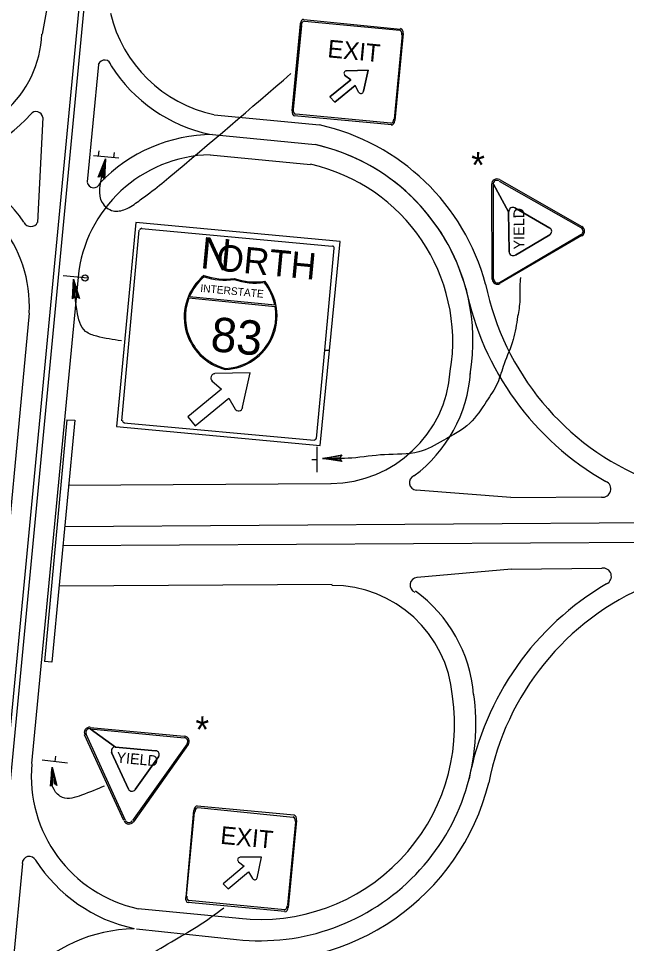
# Model space of a CAD drawing. Extents: x 640994 to 644422, y 298458 to 299646.
# Drawn here: x 641393.3 to 641528.1, y 298657.8 to 298862.8 of the extents above; entities that cross this region are included whole.
import ezdxf

# ---------------------------------------------------------------- set-up
doc = ezdxf.new("R2010")
doc.units = 0
doc.layers.add('2', color=7, linetype='Continuous')

msp = doc.modelspace()

# ---------------------------------------------------------------- linework, layer by layer
at = {"layer": '2'}
for p, q in [((641418.56, 298990.13), (641373.69, 298519.25)), ((641419.69, 298990.13), (641374.81, 298519.25)), ((641404.81, 298894.25), (641398.56, 298859.38)), ((641456.56, 298862.63), (641477.94, 298860.5)), ((641456.69, 298862.25), (641477.81, 298860.25)), ((641453.94, 298842.38), (641455.81, 298861.63)), ((641454.19, 298842.63), (641456.06, 298861.25)), ((641456.06, 298861.25), (641454.19, 298842.63)), ((641476.19, 298860.5), (641476.19, 298860.5)), ((641478.31, 298859.25), (641476.56, 298840.5)), ((641478.56, 298859.5), (641476.69, 298840.25)), ((641411.06, 298852.63), (641408.56, 298826.63)), ((641411.06, 298852.63), (641411.06, 298852.63)), ((641466.94, 298849.25), (641465.56, 298850.25)), ((641465.56, 298850.25), (641466.94, 298849.25)), ((641466.06, 298851.25), (641470.81, 298851.38)), ((641470.81, 298851.38), (641466.06, 298851.25)), ((641470.81, 298851.38), (641469.81, 298846.75)), ((641469.81, 298846.75), (641470.81, 298851.38)), ((641462.31, 298845.5), (641466.94, 298849.25)), ((641466.94, 298849.25), (641462.31, 298845.5)), ((641467.94, 298848), (641463.44, 298844.25)), ((641463.44, 298844.25), (641467.94, 298848)), ((641468.69, 298846.5), (641467.94, 298848)), ((641467.94, 298848), (641468.69, 298846.5)), ((641469.81, 298846.75), (641469.81, 298846.75)), ((641463.44, 298844.25), (641462.31, 298845.5)), ((641462.31, 298845.5), (641463.44, 298844.25)), ((641475.81, 298839.63), (641454.81, 298841.63)), ((641398.69, 298840.88), (641397.56, 298817.63)), ((641436.69, 298841.5), (641460.06, 298839.25)), ((641476.06, 298839.25), (641454.44, 298841.25)), ((641436.31, 298837.11), (641459.06, 298834.88)), ((641411.06, 298832.38), (641411.19, 298833.5)), ((641415.56, 298831.88), (641409.94, 298832.38)), ((641414.44, 298832), (641414.56, 298833.13)), ((641435.81, 298832.63), (641458.06, 298830.5)), ((641408.56, 298826.63), (641408.56, 298826.63)), ((641498.31, 298805), (641498.19, 298826.13)), ((641498.56, 298805), (641498.56, 298826.13)), ((641501.94, 298820), (641498.56, 298826.13)), ((641501.94, 298820), (641498.56, 298826.13)), ((641498.56, 298805), (641498.56, 298826.13)), ((641498.56, 298826.13), (641501.94, 298820)), ((641499.81, 298826.75), (641517.94, 298816.5)), ((641499.81, 298826.75), (641517.94, 298816.5)), ((641499.94, 298827.13), (641518.19, 298816.75)), ((641502.06, 298811.13), (641501.94, 298820)), ((641501.94, 298820), (641502.06, 298811.13)), ((641503.31, 298820.88), (641511.06, 298816.38)), ((641511.06, 298816.38), (641503.31, 298820.88)), ((641419.31, 298817.63), (641415.06, 298772.38)), ((641464.57, 298813.36), (641419.31, 298817.63)), ((641416.19, 298773.63), (641420.06, 298815.88)), ((641420.56, 298816.25), (641462.81, 298812.38)), ((641462.23, 298789.22), (641464.57, 298813.36)), ((641517.94, 298814.88), (641499.94, 298804.25)), ((641517.94, 298814.88), (641499.94, 298804.25)), ((641518.19, 298814.75), (641500.06, 298804.13)), ((641511.06, 298814.88), (641503.44, 298810.38)), ((641503.44, 298810.38), (641511.06, 298814.88)), ((641463.19, 298811.88), (641461.11, 298789.33)), ((641406.56, 298805.5), (641396.19, 298697.63)), ((641408.69, 298805.25), (641403.19, 298805.75)), ((641406.56, 298805.5), (641406.56, 298805.5)), ((641431.06, 298800.88), (641450.19, 298799)), ((641450.19, 298799.25), (641431.19, 298801.13)), ((641395.69, 298797.5), (641385.44, 298688.75)), ((641405.69, 298796.38), (641405.69, 298796.38)), ((641395.31, 298793), (641395.31, 298793)), ((641461.11, 298789.33), (641459.31, 298769.75)), ((641460.19, 298768.13), (641462.23, 298789.22)), ((641462.23, 298789.22), (641461.11, 298789.33)), ((641461.11, 298789.33), (641462.23, 298789.22)), ((641444.69, 298784.25), (641436.81, 298784.13)), ((641444.69, 298784.25), (641436.81, 298784.13)), ((641442.94, 298776.63), (641444.69, 298784.25)), ((641442.94, 298776.63), (641444.69, 298784.25)), ((641436.19, 298782.5), (641438.31, 298780.63)), ((641436.19, 298782.5), (641438.31, 298780.63)), ((641438.31, 298780.63), (641430.81, 298774.5)), ((641438.31, 298780.63), (641430.81, 298774.5)), ((641432.44, 298772.5), (641439.94, 298778.63)), ((641432.44, 298772.5), (641439.94, 298778.63)), ((641439.94, 298778.63), (641441.31, 298776.25)), ((641439.94, 298778.63), (641441.31, 298776.25)), ((641443.06, 298776.63), (641442.94, 298776.63)), ((641443.06, 298776.63), (641442.94, 298776.63)), ((641430.81, 298774.5), (641432.44, 298772.5)), ((641430.81, 298774.5), (641432.44, 298772.5)), ((641404.06, 298773.88), (641399.06, 298720.25)), ((641405.81, 298773.75), (641400.69, 298720.13)), ((641404.06, 298773.88), (641405.81, 298773.75)), ((641415.06, 298772.38), (641460.19, 298768.13)), ((641458.81, 298769.25), (641416.69, 298773.13)), ((641459.44, 298767.88), (641459.44, 298762.25)), ((641459.44, 298765), (641458.31, 298765)), ((641404.31, 298759.38), (641462.56, 298759.75)), ((641462.56, 298759.75), (641462.56, 298759.75)), ((641502.44, 298756.63), (641481.44, 298758.25)), ((641502.44, 298756.63), (641522.44, 298756.75)), ((641820.31, 298752.92), (641403.56, 298750.13)), ((641403.06, 298746), (641820.31, 298748.39)), ((641502.56, 298740.75), (641481.69, 298738.88)), ((641502.56, 298740.75), (641522.56, 298741)), ((641462.81, 298737.38), (641402.31, 298737)), ((641460.44, 298737.38), (641460.44, 298737.38)), ((641400.69, 298720.13), (641399.06, 298720.25)), ((641409.19, 298705.63), (641430.06, 298703.75)), ((641409.19, 298705.38), (641430.06, 298703.38)), ((641414.81, 298701.25), (641409.19, 298705.38)), ((641409.19, 298705.38), (641430.06, 298703.38)), ((641409.19, 298705.38), (641414.81, 298701.25)), ((641396.69, 298702.63), (641396.69, 298702.63)), ((641416.69, 298685), (641407.94, 298704)), ((641417.06, 298685), (641408.31, 298704.13)), ((641417.06, 298685), (641408.31, 298704.13)), ((641417.69, 298692), (641413.94, 298700.13)), ((641413.94, 298700.13), (641417.69, 298692)), ((641414.81, 298701.25), (641414.81, 298701.38)), ((641414.81, 298701.25), (641423.69, 298700.5)), ((641423.69, 298700.5), (641414.81, 298701.25)), ((641430.69, 298702), (641418.56, 298685)), ((641430.69, 298702), (641418.56, 298685)), ((641430.94, 298701.88), (641418.81, 298684.75)), ((641404.19, 298697.75), (641398.56, 298698.38)), ((641401.44, 298698.13), (641401.56, 298699.25)), ((641424.31, 298699.13), (641419.19, 298691.88)), ((641419.19, 298691.88), (641424.31, 298699.13)), ((641418.94, 298697.5), (641418.94, 298697.5)), ((641432.94, 298688.25), (641454.44, 298686.25)), ((641433.06, 298687.88), (641454.19, 298685.75)), ((641430.44, 298668), (641432.19, 298687.25)), ((641430.56, 298668.25), (641432.31, 298686.88)), ((641454.69, 298684.75), (641452.94, 298666.25)), ((641454.94, 298685), (641453.06, 298665.75)), ((641394.19, 298675.5), (641391.81, 298650.75)), ((641442.06, 298675.88), (641443.31, 298674.88)), ((641447.19, 298676.88), (641442.44, 298676.88)), ((641446.19, 298672.25), (641447.19, 298676.88)), ((641443.31, 298674.88), (641438.69, 298671)), ((641439.81, 298669.88), (641444.31, 298673.63)), ((641444.31, 298673.63), (641445.19, 298672.13)), ((641438.69, 298671), (641439.81, 298669.88)), ((641419.81, 298665.5), (641442.19, 298663.38)), ((641452.31, 298664.88), (641430.94, 298666.88)), ((641452.31, 298665.25), (641431.06, 298667.25)), ((641419.44, 298661), (641441.64, 298658.64))]:
    msp.add_line(p, q, dxfattribs=at)
for points in [[(641411.15, 298827.77), (641411.43, 298827.79), (641412.59, 298831.69), (641411.15, 298827.77), (641410.94, 298827.64), (641412.59, 298831.69), (641411.94, 298827.66), (641412.18, 298827.51), (641412.59, 298831.69), (641412.37, 298827.19), (641412.18, 298827.51)], [(641405.47, 298800.89), (641405.72, 298801), (641405.47, 298805.07), (641405.47, 298800.89), (641405.31, 298800.69), (641405.47, 298805.07), (641406.25, 298801.06), (641406.52, 298801), (641405.47, 298805.07), (641406.81, 298800.76), (641406.52, 298801)], [(641464.81, 298764.88), (641464.69, 298765.13), (641460.69, 298765.25), (641464.81, 298764.88), (641464.94, 298764.63), (641460.69, 298765.25), (641464.69, 298765.5), (641464.81, 298765.88), (641460.69, 298765.25), (641464.94, 298766.13), (641464.81, 298765.88)], [(641400.56, 298692.88), (641400.94, 298693.13), (641400.81, 298696.88), (641400.56, 298692.88), (641400.44, 298692.63), (641400.81, 298696.88), (641401.31, 298693.13), (641401.69, 298693), (641400.81, 298696.88), (641401.81, 298692.75), (641401.69, 298693)]]:
    msp.add_lwpolyline(points, dxfattribs=at)
msp.add_circle((641408.07, 298805.32), 0.685, dxfattribs=at)
for centre, radius, start, end in [((641442.98, 298870.96), 30.1, 193.3923, 257.789), ((641374.47, 298860.26), 24.02, 264.6308, 357.9333), ((641412.39, 298852.16), 1.47, 7.1345, 160.9311), ((641442.98, 298870.96), 34.57, 212.5881, 257.7912), ((641466.01, 298850.69), 0.559, 89.4252, 230.0907), ((641466.01, 298850.69), 0.559, 89.4252, 230.0907), ((641469.21, 298846.77), 0.559, 207.8136, 351.7203), ((641469.21, 298846.77), 0.559, 207.8136, 351.7203), ((641374.47, 298860.26), 28.5, 264.6308, 319.1479), ((641397.22, 298840.65), 1.53, 9.3098, 140.8858), ((641449.28, 298791.2), 49.23, 14.982, 77.4127), ((641436.47, 298802.54), 34.57, 90.2672, 136.5449), ((641449.28, 298791.2), 44.75, 350.6257, 77.4127), ((641449.28, 298791.2), 44.75, 14.982, 77.4127), ((641367.06, 298799.09), 33.15, 34.0358, 81.3457), ((641436.47, 298802.54), 30.09, 91.3419, 174.3352), ((641449.28, 298791.2), 40.27, 350.6257, 77.4127), ((641367.06, 298799.09), 28.67, 356.9079, 81.3457), ((641499.33, 298826.08), 1.18, 60.3746, 180.3747), ((641409.97, 298826.77), 1.47, 188.202, 341.9985), ((641499.33, 298826.08), 0.871, 60.3746, 180.3747), ((641499.33, 298826.08), 0.871, 60.3746, 180.3747), ((641502.86, 298820.07), 0.871, 60.3747, 180.3747), ((641502.86, 298820.07), 0.871, 60.3747, 180.3747), ((641396.03, 298818.37), 1.67, 206.0643, 335.1102), ((641420.61, 298815.91), 0.42, 84.742, 174.8057), ((641510.61, 298815.66), 0.871, 300.3747, 60.3746), ((641510.61, 298815.66), 0.871, 300.3747, 60.3746), ((641517.58, 298815.7), 0.871, 300.3747, 60.3746), ((641517.58, 298815.7), 0.871, 300.3747, 60.3746), ((641517.58, 298815.7), 1.18, 300.3747, 60.3746), ((641462.86, 298811.95), 0.42, 354.0939, 85.0303), ((641502.91, 298811.14), 0.871, 180.3746, 300.3746), ((641502.91, 298811.14), 0.871, 180.3746, 300.3746), ((641442.02, 298796.64), 11.97, 129.5662, 256.4361), ((641442.02, 298796.64), 11.72, 130.2586, 157.7735), ((641439.03, 298818.82), 13.76, 250.3162, 278.8163), ((641439.03, 298818.82), 14.01, 250.9067, 278.5552), ((641445.77, 298818.18), 14.01, 250.5773, 278.2257), ((641445.77, 298818.18), 13.76, 250.3162, 278.8163), ((641499.47, 298805.09), 1.18, 180.3747, 300.3747), ((641499.47, 298805.09), 0.871, 180.3746, 300.3747), ((641499.47, 298805.09), 0.871, 180.3746, 300.3747), ((641438.65, 298796.96), 11.97, 272.6963, 39.5662), ((641438.65, 298796.96), 11.72, 11.359, 38.8739), ((641555.3, 298815.87), 64.14, 191.542, 240.2801), ((641555.3, 298815.87), 59.66, 191.542, 247.9601), ((641442.02, 298796.64), 11.72, 159.0531, 256.4361), ((641438.65, 298796.96), 11.72, 272.6964, 10.0794), ((641462.28, 298786.52), 26.8, 270.6921, 355.9731), ((641462.28, 298786.52), 31.28, 306.6668, 355.9731), ((641436.85, 298783.16), 0.916, 89.4252, 230.0907), ((641436.85, 298783.16), 0.916, 89.4252, 230.0907), ((641442.1, 298776.74), 0.916, 207.8136, 351.7203), ((641442.1, 298776.74), 0.916, 207.8136, 351.7203), ((641416.75, 298773.67), 0.42, 175.1355, 263.8845), ((641458.88, 298769.81), 0.42, 265.3331, 354.8056), ((641481.63, 298759.91), 1.69, 113.864, 263.9377), ((641522.78, 298758.51), 1.81, 261.3339, 66.4393), ((641522.9, 298739.16), 1.81, 294.3091, 99.4145), ((641462.78, 298710.36), 26.8, 4.7753, 90.0563), ((641481.78, 298737.22), 1.69, 96.8106, 246.8843), ((641556.17, 298682.23), 64.14, 120.4682, 169.2063), ((641556.17, 298682.23), 59.66, 112.7883, 169.2063), ((641462.78, 298710.36), 31.51, 4.7753, 54.0816), ((641446.85, 298706.2), 47.84, 263.7511, 8.5263), ((641446.85, 298706.2), 43.11, 263.7511, 8.5263), ((641409.08, 298704.52), 1.18, 84.5662, 204.5663), ((641409.08, 298704.52), 0.871, 84.5662, 204.5663), ((641409.08, 298704.52), 0.871, 84.5662, 204.5663), ((641429.98, 298702.53), 0.871, 324.5662, 84.5662), ((641429.98, 298702.53), 0.871, 324.5662, 84.5662), ((641429.98, 298702.53), 1.18, 324.5662, 84.5662), ((641414.76, 298700.48), 0.871, 84.5662, 204.5662), ((641414.76, 298700.48), 0.871, 84.5662, 204.5662), ((641423.65, 298699.63), 0.871, 324.5663, 84.5662), ((641423.65, 298699.63), 0.871, 324.5663, 84.5662), ((641426.23, 298694.87), 30.09, 174.798, 257.7913), ((641418.47, 298692.36), 0.871, 204.5663, 324.5662), ((641418.47, 298692.36), 0.871, 204.5663, 324.5662), ((641446.85, 298706.2), 52.3, 263.7511, 345.8438), ((641417.81, 298685.42), 1.18, 204.5663, 324.5662), ((641417.81, 298685.42), 0.871, 204.5663, 324.5662), ((641417.81, 298685.42), 0.871, 204.5663, 324.5662), ((641395.72, 298675.49), 1.58, 26.5185, 181.1633), ((641426.23, 298694.87), 34.57, 212.5883, 257.7913), ((641442.43, 298676.33), 0.55, 90, 232.4314), ((641445.68, 298672.41), 0.55, 209.6455, 347.0123), ((641419.72, 298626.46), 34.57, 91.3421, 136.5451)]:
    msp.add_arc(centre, radius, start, end, dxfattribs=at)
for centre, major_axis, start_param, end_param in [((641456.41, 298861.57), (-0.1, -1.07), 3.141593, 4.712389), ((641456.57, 298861.24), (-0.094, -0.99), 3.141593, 4.712389), ((641477.68, 298859.23), (0.094, 0.99), 4.712389, 6.283185), ((641477.9, 298859.53), (0.1, 1.07), 4.712389, 6.283185), ((641454.58, 298842.31), (-0.1, -1.07), 4.712389, 6.283185), ((641454.8, 298842.61), (-0.094, -0.99), 4.712389, 6.283185), ((641475.9, 298840.6), (0.094, 0.99), 3.141593, 4.712389), ((641476.06, 298840.27), (0.1, 1.07), 3.141593, 4.712389), ((641432.82, 298687.17), (-0.1, -1.07), 3.141593, 4.712389), ((641432.98, 298686.84), (-0.094, -0.99), 3.141593, 4.712389), ((641454.08, 298684.83), (0.094, 0.99), 4.712389, 6.283185), ((641454.3, 298685.13), (0.1, 1.07), 4.712389, 6.283185), ((641430.99, 298667.91), (-0.1, -1.07), 4.712389, 6.283185), ((641431.21, 298668.21), (-0.094, -0.99), 4.712389, 6.283185), ((641452.31, 298666.2), (0.094, 0.99), 3.141593, 4.712389), ((641452.47, 298665.87), (0.1, 1.07), 3.141593, 4.712389)]:
    msp.add_ellipse(centre, major_axis=major_axis, ratio=0.6, start_param=start_param, end_param=end_param, dxfattribs=at)
for points in [[(641412.17, 298829.75), (641411.81, 298828.25), (641411.84, 298822.03), (641414.26, 298820.19), (641417.02, 298820.55), (641419.98, 298822.37), (641422.43, 298824.18), (641426.64, 298827.57), (641453.69, 298850.63)], [(641504.56, 298805.38), (641504.44, 298803.5), (641504.44, 298800.38), (641503.94, 298796.75), (641502.94, 298791.63), (641500.94, 298786.25), (641499.44, 298782), (641497.06, 298778), (641493.31, 298773.13), (641487.44, 298769.25), (641482.06, 298766.75), (641474.44, 298766.13), (641467.19, 298765.38), (641460.69, 298765.25)], [(641416.11, 298791.37), (641410.66, 298792.37), (641408.18, 298793.46), (641406.3, 298797.97), (641405.56, 298804.5)], [(641412.31, 298692.63), (641407.31, 298690.63), (641403.06, 298690.13), (641401.19, 298691.88), (641400.81, 298696.88)], [(641394.56, 298653.56), (641394.35, 298651.89), (641394.44, 298647.29), (641396.89, 298645.56), (641398.8, 298645.69), (641402.25, 298646.14), (641405.09, 298646.96), (641410.63, 298648.71), (641414.66, 298650.8), (641420.94, 298654.38), (641427.19, 298658.13), (641433.06, 298661.63), (641438.81, 298665.63)]]:
    msp.add_spline(points, degree=3, dxfattribs=at)

# ---------------------------------------------------------------- texts
for s, height, rotation, p in [('EXIT', 3.917, 354.566, (641461.69, 298854.25)), ('YIELD', 2.383, 90.3738, (641505.44, 298811.63)), ('N', 6.97, 354.5817, (641433.44, 298807.5)), ('ORTH', 5.85, 354.5683, (641436.94, 298807)), ('INTERSTATE', 1.693, 354.5666, (641433.56, 298802.25)), ('83', 7.618, 354.5657, (641435.69, 298789.13)), ('YIELD', 2.383, 354.5663, (641414.94, 298697.88)), ('EXIT', 3.917, 354.566, (641437.94, 298679.88))]:
    msp.add_text(s, height=height, rotation=rotation, dxfattribs=at).set_placement(p)
for p in [(641493.64, 298827.42), (641432.53, 298702.28)]:
    msp.add_text('*', height=5.85, dxfattribs=at).set_placement(p)

doc.saveas('drawing.dxf')
